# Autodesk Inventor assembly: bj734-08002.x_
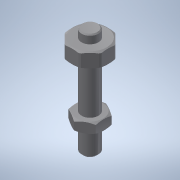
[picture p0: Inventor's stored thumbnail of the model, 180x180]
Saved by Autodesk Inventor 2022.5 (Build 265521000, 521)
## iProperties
Part Number: bj734-08002.x_
Material: 一般
Document SubType Name: Assembly
Designer: ImaoCorp
Sending System: SOLIDWORKS 2017-2017317
MC: AMD64
MC_MODEL: Intel64 Family 6 Model 60 Stepping 3, GenuineIntel
OS: Windows_NT
FRU: Parasolid Version 29.0, build 201,  4-17-2017
FORMAT: text
GUISE: transmit
KEY: bj734-08002
FILE: bj734-08002.x_t
DATE: Fri Mar 15 10:10:03 2019
Author: ImaoCorp
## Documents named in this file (3)
- X:\14_SW2022-Inv2022\00_全2023-1023新製品(TCC)まで\b\bj734-08002\BJ734-08002.iam
- X:\14_SW2022-Inv2022\00_全2023-1023新製品(TCC)まで\b\bj734-08002\bj734-08002_01.ipt
- X:\14_SW2022-Inv2022\00_全2023-1023新製品(TCC)まで\b\bj734-08002\bj734-08002_02.ipt
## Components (2 placed, 2 different names)
1. bj734-08002_01
2. bj734-08002_02
